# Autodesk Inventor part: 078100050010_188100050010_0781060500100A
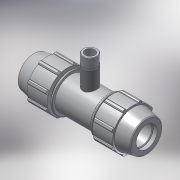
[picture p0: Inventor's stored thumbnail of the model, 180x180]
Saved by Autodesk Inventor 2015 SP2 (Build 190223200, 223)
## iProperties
Created: 2017-02
Part Number: 078100050010_188100050010_0781060500100A
Material: PVC-Piping
Description: PLASSON COUPLER WITH RISER 50-1"
Document SubType Name: Modeling
Designer: KIM
Mass: 92.6774 g
Surface Area: 199.44 cm^2
Volume: 66.1981 cm^3
Density: 1.4 g/cm^3
Appearance: Smooth - White
Author: Кирилл
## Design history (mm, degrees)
derived "07810.ipt"
feature "Solid1::07810.ipt"
feature "Solid2::07810.ipt"
tag "TaggingFeature1"
body "Solid1"
other parameters: "d4" = 10.16667, "d5" = 29.28, "d7" = 96, "d11" = 4.06667, "d13" = 120 deg, "d15" = 12 deg, "d16" = 83.52, "d18" = 2.5, "d19" = 35 deg, "d20" = 17.5 deg, "d21" = 89.28, "d23" = 0, "d25" = 360 deg, "d27" = 1.92, "d33" = 1, "d42" = 43.92, "d43" = 2.88, "d46" = 1.5, "d68" = 4.06667, "d73" = 33.249, "d76" = 23.2743, "d77" = 24, "d80" = 0.99747, "d91" = 72, "d93" = 98, "d95" = 45, "d99" = 244, "d101" = 0, "d103" = 0, "d105" = 0, "d106" = 33.91398, "E_" = 96, "l_" = 98, "H_" = 244, "R_" = 33.249
